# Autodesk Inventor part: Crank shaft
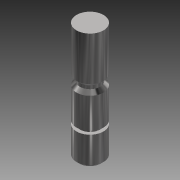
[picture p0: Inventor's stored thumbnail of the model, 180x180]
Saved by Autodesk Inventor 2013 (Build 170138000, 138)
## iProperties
Created: 2008-06
Part Number: Crank shaft
Document SubType Name: Modeling
Designer: tangg
Density: 7.84 g/cm^3
Mass: 5.33262 g
Surface Area: 21.043 cm^2
Volume: 5.33262 cm^3
Material: Steel, High Strength Low Alloy
Author: tangg
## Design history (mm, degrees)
sketch "Sketch8"
  geometry: C1 r 6.35 at (0, 0) reference; 1 further point
extrude "Extrusion4" new body sketch "Sketch8" distance "d13" = 55; taper "d14" = 0 deg
chamfer "Chamfer2" distance "d15" = 1.27; stored, may be unused: second distance "d16" = 3.175, angle "d17" = 45 deg
sketch "Sketch9"
  geometry: L1 (-6.35, 0)-(-6.35, -53.73) reference; L2 (-4.763, -22.225)-(-4.763, -23.812); L3 (-6.35, -25.4)-(-6.35, -20.637); L4 (-6.35, -41.275)-(-4.763, -41.275); L5 (-4.763, -41.275)-(-4.763, -39.688); L6 (-4.763, -39.688)-(-6.35, -39.688); L7 (-6.35, -39.688)-(-6.35, -41.275); L8 (0, -64.476)-(0, 10.746) reference; L9 (-4.763, -22.225)-(-6.35, -20.637); L10 (-4.763, -23.812)-(-6.35, -25.4); 1 further point
  constraints: 16 end point, 3 point on line
revolve "Revolution1" sketch "Sketch9" stored, may be unused: angle "d18" = 90 deg
body "Solid1"
